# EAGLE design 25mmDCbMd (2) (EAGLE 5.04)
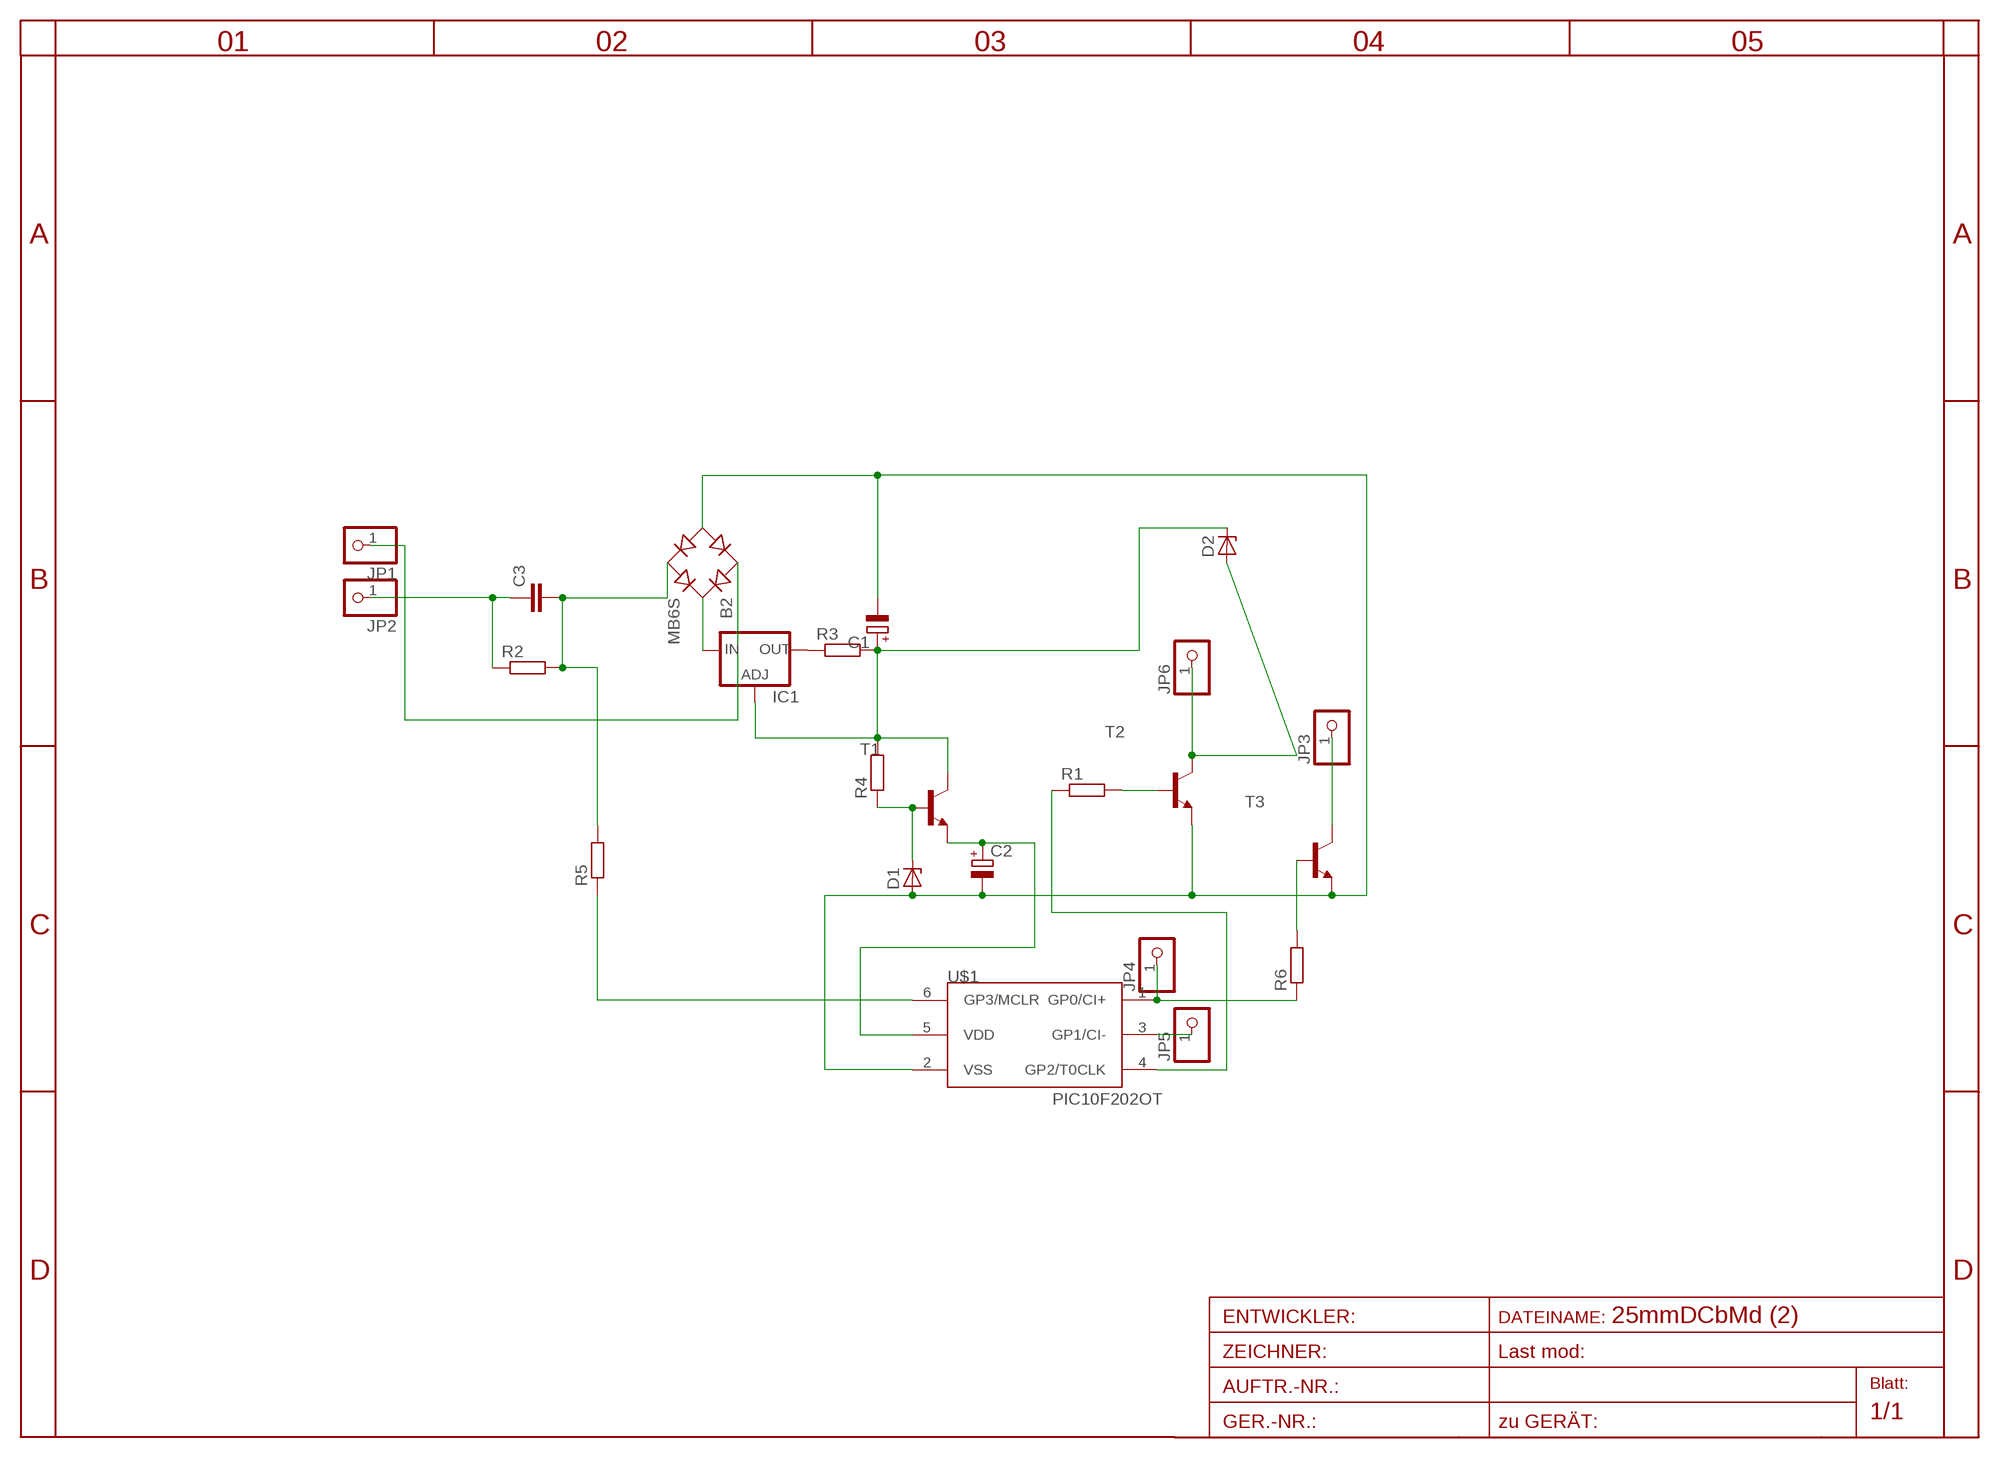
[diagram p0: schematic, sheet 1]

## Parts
B2  MB6S  [SOIC-4]
C1  CPOL-EUE5-8.5  [E5-8,5]
C2  CPOL-EUE2.5-6  [E2,5-6]
C3  C-EU102-064X133  [C102-064X133]
D1  ZENER-DIODESOT23  [SOT23]
D2  ZENER-DIODESOT23  [SOT23]
IC1  LM317LZ  [317L]
JP1  PINHD-1X1  [1X01]
JP2  PINHD-1X1  [1X01]
JP3  PINHD-1X1  [1X01]
JP4  PINHD-1X1  [1X01]
JP5  PINHD-1X1  [1X01]
JP6  PINHD-1X1  [1X01]
R1  R-EU_R0805  [R0805]
R2  R-EU_R1206  [R1206]
R3  R-EU_R0805  [R0805]
R4  R-EU_R0805  [R0805]
R5  R-EU_R0805  [R0805]
R6  R-EU_R0805  [R0805]
T1  BC846BLT1-NPN-SOT23-BEC  [SOT23-BEC]
T2  BC846BLT1-NPN-SOT23-BEC  [SOT23-BEC]
T3  BC846BLT1-NPN-SOT23-BEC  [SOT23-BEC]
U$1  PIC10F202OT  [SOT23-6]

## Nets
AC: B2.~1(AC1) JP1.1
AC+: C3.1 JP2.1 R2.1
LOAD/COIL: D2.1(A) JP6.1 T2.C
MINUS: B2.- C1.- C2.- D1.1(A) T2.E T3.E U$1.2(VSS)
N$1: B2.~2(AC2) C3.2 R2.2 R5.2
N$2: B2.+ IC1.3(IN)
N$3: R5.1 U$1.6(GP3/MCLR)
N$4: R6.2 T3.B
N$5: IC1.2(OUT) R3.1
N$6: D1.3(C) R4.1 T1.B
N$8: R1.2 T2.B
N$9: JP3.1 T3.C
N$11: R1.1 U$1.4(GP2/T0CLK)
N$12: JP4.1 R6.1 U$1.1(GP0/CI+)
N$13: JP5.1 U$1.3(GP1/CI-)
PLUS: C1.+ D2.3(C) IC1.1(ADJ) R3.2 R4.2 T1.C
VDD: C2.+ T1.E U$1.5(VDD)

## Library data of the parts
B2 = rectifier:MB*S: Bridge Rectifier Source: http://www.fairchildsemi.com/ds/MB/MB6S.pdf
C1 = rcl-2:CPOL-EU: POLARIZED CAPACITOR, European symbol
C2 = rcl:CPOL-EU: POLARIZED CAPACITOR, European symbol
C3 = rcl:C-EU: CAPACITOR, European symbol
D1 D2 = diode-1:ZENER-DIODE: Z-Diode
IC1 = v-reg-3:LM317L: Adjustable Voltage Regulator, 1.2V to 37V, 100mA
JP1-JP6 = pinhead:PINHD-1X1: PIN HEADER
R1-R6 = rcl:R-EU_: RESISTOR, European symbol
T1-T3 = transistor:*-NPN-: NPN Transistror BF959 corrected 2008.03.06
U$1 = microchip-5:PIC10F2*: uPC nW 0,25/0,5k Program Flash memory Comparator

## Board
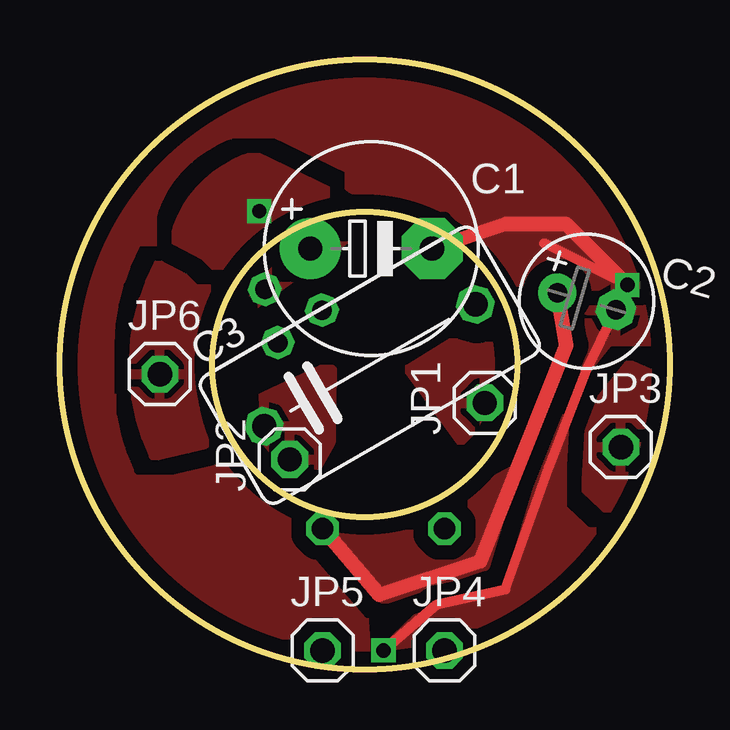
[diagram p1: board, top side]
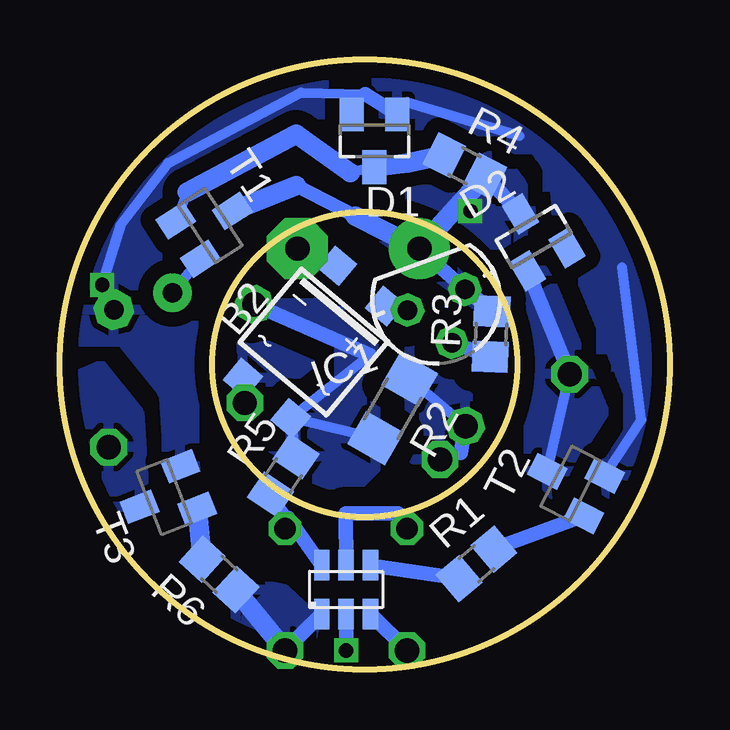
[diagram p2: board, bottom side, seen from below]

Size 25.4 x 25.4 mm. Coordinates in mm from the lower left corner, seen from the top.
Outline: circle at 12.7,12.7 radius 12.7
Outline: circle at 12.7,12.7 radius 6.35
Copper layers (1*16): Top 0.035mm / dielectric 1.5mm / Bottom 0.035mm
Design rules "default *": minimum track width 10mil, minimum drill 24mil, track to track 8mil, track to pad 8mil, pad to pad 8mil, via to via 8mil, smd to smd 8mil, copper to edge 4mil, drill to drill 8mil, minimum pad ring 10mil, minimum via ring 8mil, stop-mask expansion 4mil, vias tented up to drill 0mil, thermal gap 10mil

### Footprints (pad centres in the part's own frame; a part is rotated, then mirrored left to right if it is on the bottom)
SOIC-4 = smd 1.2 x 1.2: + 1.3,3.05; - -1.3,3.05; ~1 -1.3,-3.05; ~2 1.3,-3.05
E5-8,5 = drill 1.016 pad 2.54 round: + -2.54,0 | drill 1.016 pad 2.54 octagon: - 2.54,0
E2,5-6 = drill 0.813 pad 1.6 round: + -1.27,0 | drill 0.813 pad 1.6 octagon: - 1.27,0
C102-064X133 = drill 1.016 octagon: 1 -5.08,0; 2 5.08,0
SOT23 = smd 1 x 1.4: 1 -0.95,-1.1; 2 0.95,-1.1; 3 0,1.1
317L = drill 0.813 octagon: 1 -1.27,0; 2 0,1.905; 3 1.27,0
1X01 = drill 1.016 octagon: 1 0,0
R0805 = smd 1.3 x 1.5: 1 -0.95,0; 2 0.95,0
R1206 = smd 1.6 x 1.803: 1 -1.422,0; 2 1.422,0
SOT23-BEC = smd 1 x 1.4: B -0.95,-1.1; C 0,1.1; E 0.95,-1.1
SOT23-6 = smd 0.635 x 1.27: 1 -1.016,-1.016; 2 0,-1.016; 3 1.016,-1.016; 4 1.016,1.016; 5 0,1.016; 6 -1.016,1.016

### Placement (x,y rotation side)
B2  14.82,13.64 320 bottom
C1  12.97,17.54 0 top
C2  21.94,15.34 343.7 top
C3  12.91,12.67 30 top
D1  12.3,22.03 180 bottom
D2  5.65,18.04 30.4 bottom
IC1  9.73,15.4 200.1 bottom
JP1  17.7,11.1 90 top
JP2  9.57,8.74 90 top
JP3  23.37,9.26 0 top
JP4  16.02,0.78 0 top
JP5  10.94,0.78 0 top
JP6  4.16,12.3 0 top
R1  8.05,4.39 40.3 bottom
R2  11.54,10.86 240 bottom
R3  7.44,13.98 87.6 bottom
R4  8.54,21 332.8 bottom
R5  16.1,8.07 56.2 bottom
R6  18.77,3.95 137.6 bottom
T1  19.14,18.5 303 bottom
T2  4.12,7.74 62.7 bottom
T3  21.06,7.17 111.3 bottom
U$1  13.48,3.32 0 bottom

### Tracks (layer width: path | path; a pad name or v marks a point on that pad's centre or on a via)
AC
  Bottom 0.406: B2.~1 JP1.1
  pour Bottom (isolate 0.813, rank 2): 18.56,13.48 18.7,14.3 17.1,14.1 14.3,12.9 17.9,10.7 18.9,11.1
  pour Top (isolate 0.813, rank 2): 18.36,13.28 17.7,14.1 17.1,14.1 14.5,12.5 16.7,9.5 18.1,10.9
AC+
  Bottom 0.406: C3.1 R2.1 | 8.71,9.01 JP2.1
  Bottom 0.61: C3.1 8.71,9.01
  pour Bottom (isolate 0.813): 10.94,13.48 10.48,13.48 7.1,10.1 7.1,9.5 9.3,7.3 11.1,9.1
  pour Top (isolate 0.813): 11.34,12.48 10.88,12.48 7.5,10.9 8.5,8.9 10.3,7.7 11.3,9.5
LOAD/COIL
  Bottom 0.406: T2.C JP6.1
  Bottom 0.61: JP6.1 D2.1
  pour Bottom (isolate 0.61, rank 4): 2.7,10.7 4.9,7.3 5.86,8.4 5.86,18.42
  pour Top (isolate 0.61, rank 4): 4.1,16.9 arc53 3.9,8.9 6.06,9.4 arc-48 6.26,16.02
MINUS  (via drill 0.6)
  Top 0.406: v13.48,0.78 15.7,2.7 18.56,3.32 20.36,8.4 21.9,12.4 C2.- | v23.64,16.02 20.16,17.76
  Top 0.61: C1.- 18.56,18.56 21.1,18.56 v23.64,16.02
  Bottom 0.406: T2.E 1.18,10.4 1.98,16.76 | 6.26,22.24 10.94,23.64 D1.1 | 12.68,23.98 15.36,24.04 20.9,21.1 22.84,18.56 v23.64,16.02 23.44,15.28 C2.-
  Bottom 0.61: U$1.2 v13.48,0.78 | 12.68,23.98 D1.1 | C1.- B2.-
  pour Bottom (isolate 0.61, rank 5): 2.58,6.8 -0.36,11.14 0.78,21.1 10.94,26.18 23.64,23.64 26.18,10.94 22.24,7.86 19.76,8.4 19.9,19.7 13.48,23.64 5.86,21.1 3.32,13.48
  pour Top (isolate 0.61, rank 5): 0.3,15.48 arc-55 10.94,26.18 arc-42 24.64,18.64 arc-89 21.98,4.46 arc-50 13.48,0.78 15.9,3.1 18.76,5.36 21.36,11.4 21.5,12.94 21.3,14.34 15.5,17.7 11.28,20.64 12.74,0.84 arc-110
N$1
  Bottom 0.406: R2.2 B2.~2 | B2.~2 12.5,13.1 | B2.~2 R5.2
  Bottom 0.61: 12.5,13.1 C3.2
  pour Bottom (isolate 0.813, rank 3): 16.02,16.02 13.48,16.02 10.94,13.48 10.94,9.66 13.7,6.9 15.5,6.9 17.5,8.9
N$2
  Bottom 0.406: IC1.3 B2.+
N$3
  Bottom 0.406: 15.9,6.3 R5.1
  Bottom 0.61: U$1.6 15.9,6.3
N$4
  Bottom 0.813: R6.2 T3.B
N$5
  Bottom 0.61: R3.1 IC1.2
N$6
  Bottom 0.406: D1.3 13.3,20.7 | 20.1,19.9 T1.B
  Bottom 0.813: R4.1 10.94,21.1 D1.3 | 13.3,20.7 15.56,22.3 20.1,19.9
N$7  (via drill 0.9)
  other vias: 16.02,5.86
N$8
  Bottom 0.61: T2.B R1.2
N$9
  pour Bottom (isolate 0.61): 23.64,5.86 25.1,12.1 23.7,12.7 22.1,10.7 21.9,7.5
  pour Top (isolate 0.61): 23.64,5.86 25.1,12.1 23.7,12.7 22.1,10.7 21.9,7.5
N$11
  Bottom 0.61: R1.1 U$1.4
N$12
  Bottom 0.61: U$1.1 JP4.1
  Bottom 0.813: JP4.1 R6.1
  pour Bottom (isolate 0.61): 16.02,3.32 17.9,3.7 18.5,1.5 15.1,0.5 14.7,2.1
N$13
  Bottom 0.61: JP5.1 U$1.3
PLUS  (via drill 0.6)
  Bottom 0.61: C1.+ IC1.1 R3.2 | 13.1,18.9 15.56,20.16 | R4.2 D2.3
  Bottom 0.813: R4.2 C1.+ 13.1,18.9 | 15.56,20.16 T1.C
  other vias: 8.3,19.1
  pour Bottom (isolate 0.61): 5.86,18.56 arc-72 7.5,21.3 13.1,18.9 8.1,15.3 6.1,17.3
  pour Top (isolate 0.61): 4.86,17.96 arc-59 8.1,21.3 13.1,18.9 8.1,15.3 6.1,17.3
VDD  (via drill 0.9)
  Top 0.61: C2.+ 21.1,13.5 17.5,4.5 13.3,3.1 v10.94,5.86
  Bottom 0.406: C2.+ T1.E
  Bottom 0.61: v10.94,5.86 11.3,6.5 13.5,6.5 U$1.5
  pour Top (isolate 0.61): 10.94,5.86 13.7,5.5 18.9,8.3 17.7,4.3 13.5,2.9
